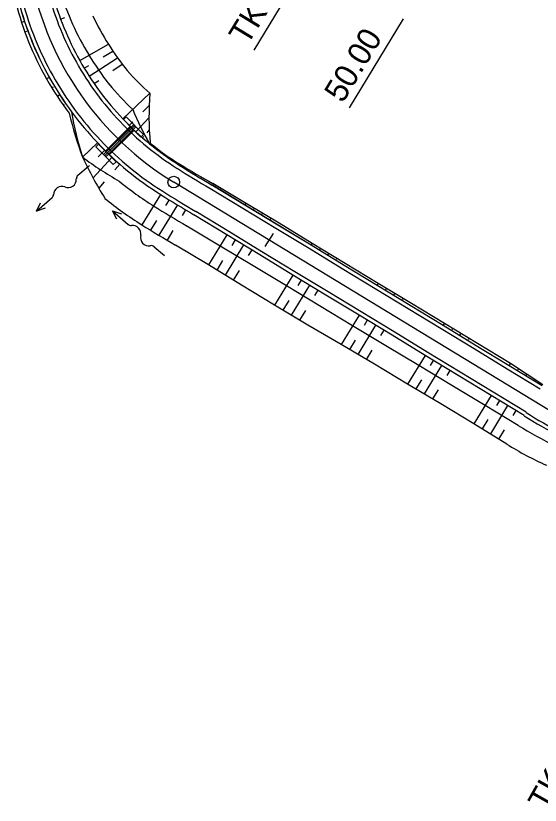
# Model space of a CAD drawing. Extents: x -481656 to -478728, y -1113199 to -1110710.
# Drawn here: x -479818.4 to -479750.6, y -1112835 to -1112732.9 of the extents above; entities that cross this region are included whole.
import ezdxf

# ---------------------------------------------------------------- set-up
doc = ezdxf.new("R2010")
doc.units = 0
for name, color, linetype in [('C1_HATCH_SLOPE_L', 7, 'Continuous'), ('C1_HATCH_SLOPE_R', 7, 'Continuous'), ('C1_HLBODY', 7, 'Continuous'), ('C1_HRANA_TELESO', 7, 'Continuous'), ('C1_KORUNA', 7, 'Continuous'), ('C1_OSA', 7, 'Continuous'), ('C1_PRIKOP', 7, 'Continuous'), ('C1_STANICENI', 7, 'Continuous'), ('C1_VOZOVKA', 7, 'Continuous'), ('C1_ZPEVKRAJ', 7, 'Continuous'), ('DRENÁŽ', 7, 'Continuous'), ('PLYN', 7, 'Continuous'), ('ŽLAB', 7, 'Continuous')]:
    doc.layers.add(name, color=color, linetype=linetype)

# ---------------------------------------------------------------- blocks, each defined once
blk = doc.blocks.new('A$C716')
at = {"layer": 'ŽLAB'}
for p, q in [((-5.015, 2.333), (-4.471, 3.623)), ((-4.01, 3.428), (-4.554, 2.138)), ((-4.01, 3.428), (-4.471, 3.623)), ((-5.17, 1.964), (-5.015, 2.333)), ((0, 0), (-5.093, 2.148)), ((-5.015, 2.333), (-0.383, 0.379)), ((-4.554, 2.138), (-5.015, 2.333)), ((-0.325, 0.517), (-4.496, 2.277)), ((-5.715, 0.674), (-5.17, 1.964)), ((-4.71, 1.77), (-5.254, 0.48)), ((-0.078, -0.184), (-5.171, 1.964)), ((-4.71, 1.77), (-5.17, 1.964)), ((-4.768, 1.632), (-0.597, -0.128)), ((0.161, 1.669), (-0.383, 0.379)), ((0.078, 0.184), (0.622, 1.474)), ((0.161, 1.669), (0.622, 1.474)), ((-5.254, 0.48), (-5.715, 0.674)), ((-0.538, 0.01), (-1.083, -1.28)), ((-0.078, -0.184), (-0.999, 0.204)), ((0.078, 0.184), (-0.844, 0.573)), ((-0.538, 0.01), (-0.383, 0.379)), ((-0.078, -0.184), (0.078, 0.184)), ((-0.622, -1.474), (-0.078, -0.184)), ((-1.083, -1.28), (-0.622, -1.474))]:
    blk.add_line(p, q, dxfattribs=at)
blk = doc.blocks.new('A$C70B')
at = {"layer": 'DRENÁŽ'}
for p, q in [((0.87, 0), (-0.87, 0)), ((6.86, 0.43), (7.97, 0)), ((7.97, 0), (5.28, 0)), ((7.97, 0), (6.86, -0.48))]:
    blk.add_line(p, q, dxfattribs=at)
for centre, radius, start, end in [((0.87, 0.58), 0.582, 269.6924, 322.7901), ((2.17, -0.42), 1.05, 24.4039, 142.0836), ((4.08, 0.59), 1.11, 210.8873, 317.3707), ((5.32, -0.64), 0.636, 85.9766, 131.7248)]:
    blk.add_arc(centre, radius, start, end, dxfattribs=at)

msp = doc.modelspace()

# ---------------------------------------------------------------- linework, layer by layer
at = {"layer": 'C1_HATCH_SLOPE_L'}
for p, q in [((-479817.25, -1112733.66), (-479817.64, -1112733.79)), ((-479817.01, -1112734.98), (-479817.2, -1112735.05)), ((-479816.81, -1112734.91), (-479816.81, -1112734.91)), ((-479814.05, -1112740.89), (-479814.41, -1112741.09)), ((-479813.56, -1112742.14), (-479813.73, -1112742.24)), ((-479813.39, -1112742.04), (-479813.39, -1112742.04)), ((-479812.69, -1112743.16), (-479813.01, -1112743.36)), ((-479812.11, -1112744.36), (-479812.26, -1112744.47)), ((-479811.96, -1112744.26), (-479811.96, -1112744.26)), ((-479807.8, -1112749.38), (-479809.74, -1112751.22)), ((-479806.87, -1112750.32), (-479807.73, -1112751.18)), ((-479805.92, -1112751.23), (-479808.41, -1112753.91)), ((-479808.84, -1112752.31), (-479809.1, -1112752.57)), ((-479804.94, -1112752.11), (-479805.59, -1112752.86)), ((-479806.95, -1112754.42), (-479807.66, -1112755.23)), ((-479799.65, -1112756.05), (-479802.1, -1112759.96)), ((-479798.55, -1112756.72), (-479799, -1112757.46)), ((-479797.48, -1112757.37), (-479799.88, -1112761.3)), ((-479796.42, -1112758.02), (-479796.86, -1112758.75)), ((-479800.2, -1112759.42), (-479800.95, -1112760.65)), ((-479798.06, -1112760.71), (-479798.8, -1112761.94)), ((-479791.08, -1112761.26), (-479793.45, -1112765.16)), ((-479790.01, -1112761.91), (-479790.45, -1112762.63)), ((-479788.94, -1112762.56), (-479791.32, -1112766.47)), ((-479787.87, -1112763.21), (-479788.31, -1112763.93)), ((-479791.63, -1112764.58), (-479792.38, -1112765.82)), ((-479789.5, -1112765.88), (-479790.25, -1112767.12)), ((-479782.53, -1112766.46), (-479784.91, -1112770.37)), ((-479781.46, -1112767.11), (-479781.89, -1112767.81)), ((-479780.4, -1112767.76), (-479782.77, -1112771.65)), ((-479779.33, -1112768.41), (-479779.75, -1112769.1)), ((-479783.08, -1112769.76), (-479783.84, -1112771.01)), ((-479780.93, -1112771.05), (-479781.69, -1112772.3)), ((-479773.99, -1112771.66), (-479776.31, -1112775.47)), ((-479772.92, -1112772.31), (-479773.33, -1112772.99)), ((-479771.85, -1112772.96), (-479774.15, -1112776.74)), ((-479770.79, -1112773.61), (-479771.2, -1112774.28)), ((-479774.49, -1112774.88), (-479775.23, -1112776.1)), ((-479772.34, -1112776.16), (-479773.07, -1112777.37)), ((-479765.45, -1112776.85), (-479767.7, -1112780.56)), ((-479763.31, -1112778.15), (-479765.56, -1112781.85)), ((-479764.38, -1112777.5), (-479764.78, -1112778.16)), ((-479762.24, -1112778.8), (-479762.64, -1112779.46)), ((-479765.9, -1112780.01), (-479766.63, -1112781.2)), ((-479763.76, -1112781.3), (-479764.48, -1112782.49)), ((-479756.9, -1112782.05), (-479759.12, -1112785.7)), ((-479754.77, -1112783.35), (-479757, -1112787.02)), ((-479755.83, -1112782.7), (-479756.22, -1112783.34)), ((-479753.7, -1112784), (-479754.08, -1112784.63)), ((-479757.34, -1112785.17), (-479758.06, -1112786.36)), ((-479755.2, -1112786.47), (-479755.93, -1112787.68))]:
    msp.add_line(p, q, dxfattribs=at)
at = {"layer": 'C1_HATCH_SLOPE_R'}
for p, q in [((-479812.59, -1112733.35), (-479812.04, -1112733.14)), ((-479810.12, -1112738.7), (-479806.4, -1112736.61)), ((-479807.07, -1112738.24), (-479805.83, -1112737.49)), ((-479808.91, -1112740.72), (-479805.23, -1112738.35)), ((-479809.53, -1112739.72), (-479808.92, -1112739.35)), ((-479805.82, -1112740.02), (-479804.61, -1112739.19)), ((-479808.25, -1112741.7), (-479807.64, -1112741.28)), ((-479804.54, -1112746.27), (-479801.03, -1112742.94)), ((-479801.96, -1112745.34), (-479801.14, -1112744.51)), ((-479803.71, -1112747.12), (-479803.25, -1112746.65)), ((-479802.86, -1112747.93), (-479801.17, -1112746.11)), ((-479801.4, -1112748.06), (-479801.12, -1112747.74)), ((-479801.98, -1112748.72), (-479801.84, -1112748.55)), ((-479797.25, -1112752.24), (-479797.18, -1112752.12)), ((-479796.21, -1112752.87), (-479796.21, -1112752.87)), ((-479796.17, -1112752.8), (-479796.13, -1112752.74)), ((-479795.15, -1112753.52), (-479795.05, -1112753.37)), ((-479794.08, -1112754.17), (-479794.07, -1112754.17)), ((-479794.02, -1112754.08), (-479793.98, -1112754.01)), ((-479788.74, -1112757.42), (-479788.6, -1112757.19)), ((-479787.67, -1112758.07), (-479787.67, -1112758.06)), ((-479787.6, -1112757.95), (-479787.53, -1112757.84)), ((-479786.6, -1112758.72), (-479786.46, -1112758.48)), ((-479785.53, -1112759.37), (-479785.53, -1112759.36)), ((-479785.46, -1112759.24), (-479785.39, -1112759.13)), ((-479780.19, -1112762.62), (-479780.04, -1112762.37)), ((-479779.05, -1112763.14), (-479778.97, -1112763.02)), ((-479779.13, -1112763.27), (-479779.12, -1112763.26)), ((-479778.06, -1112763.92), (-479777.9, -1112763.66)), ((-479776.99, -1112764.56), (-479776.99, -1112764.56)), ((-479776.91, -1112764.43), (-479776.84, -1112764.31)), ((-479771.65, -1112767.81), (-479771.49, -1112767.55)), ((-479770.5, -1112768.33), (-479770.42, -1112768.2)), ((-479770.58, -1112768.46), (-479770.58, -1112768.46)), ((-479769.51, -1112769.11), (-479769.35, -1112768.85)), ((-479768.45, -1112769.76), (-479768.44, -1112769.76)), ((-479768.36, -1112769.62), (-479768.28, -1112769.5)), ((-479763.11, -1112773.01), (-479762.94, -1112772.74)), ((-479761.95, -1112773.52), (-479761.87, -1112773.38)), ((-479762.04, -1112773.66), (-479762.04, -1112773.65)), ((-479760.97, -1112774.31), (-479760.8, -1112774.03)), ((-479759.9, -1112774.96), (-479759.9, -1112774.95)), ((-479759.82, -1112774.81), (-479759.73, -1112774.68)), ((-479754.56, -1112778.21), (-479754.39, -1112777.92)), ((-479753.49, -1112778.85), (-479753.49, -1112778.85)), ((-479753.42, -1112778.72), (-479753.34, -1112778.6)), ((-479752.43, -1112779.51), (-479752.29, -1112779.28)), ((-479751.36, -1112780.16), (-479751.36, -1112780.15)), ((-479751.3, -1112780.06), (-479751.24, -1112779.97))]:
    msp.add_line(p, q, dxfattribs=at)
at = {"layer": 'C1_HLBODY'}
msp.add_line((-479787.57, -1112737.36), (-479772.13, -1112711.98), dxfattribs=at)
msp.add_circle((-479797.96, -1112754.44), 0.75, dxfattribs=at)
at = {"layer": 'C1_HRANA_TELESO'}
for p, q in [((-479788.6, -1112757.19), (-479792.9, -1112754.64)), ((-479784.32, -1112759.77), (-479788.6, -1112757.19)), ((-479780.04, -1112762.37), (-479784.32, -1112759.77)), ((-479793.45, -1112765.16), (-479797.73, -1112762.59)), ((-479775.77, -1112764.96), (-479780.04, -1112762.37)), ((-479789.19, -1112767.78), (-479793.45, -1112765.16)), ((-479771.49, -1112767.55), (-479775.77, -1112764.96)), ((-479784.91, -1112770.37), (-479789.19, -1112767.78)), ((-479767.22, -1112770.14), (-479771.49, -1112767.55)), ((-479762.94, -1112772.74), (-479767.22, -1112770.14)), ((-479780.62, -1112772.94), (-479784.91, -1112770.37)), ((-479776.31, -1112775.47), (-479780.62, -1112772.94)), ((-479758.66, -1112775.33), (-479762.94, -1112772.74)), ((-479754.39, -1112777.92), (-479758.66, -1112775.33)), ((-479771.99, -1112778), (-479776.31, -1112775.47)), ((-479767.7, -1112780.56), (-479771.99, -1112778)), ((-479750.2, -1112780.65), (-479754.39, -1112777.92)), ((-479763.41, -1112783.14), (-479767.7, -1112780.56)), ((-479759.12, -1112785.7), (-479763.41, -1112783.14)), ((-479754.87, -1112788.33), (-479759.12, -1112785.7))]:
    msp.add_line(p, q, dxfattribs=at)
for centre, radius, start, end in [((-479777.08, -1112720.54), 42.66, 194.5096, 201.6717), ((-479777.98, -1112718.7), 33.59, 205.0483, 212.2201), ((-479777.25, -1112720.11), 42.67, 202.2915, 209.4535), ((-479778.09, -1112718.92), 33.38, 212.0163, 219.1868), ((-479779.16, -1112718.11), 33.1, 221.4387, 228.6289), ((-479777.39, -1112719.93), 42.63, 209.7635, 216.9258), ((-479765.9, -1112745.98), 35.26, 175.0636, 185.5386), ((-479768.84, -1112735.63), 43.77, 193.085, 200.8657), ((-479777.19, -1112720.26), 37.62, 230.7293, 237.8913), ((-479768.04, -1112732.04), 45.9, 204.698, 212.2574), ((-479737.85, -1112656.13), 112.84, 238.2814, 240.8033), ((-479777.22, -1112720.23), 46.87, 230.7782, 237.9402), ((-479727.35, -1112640.88), 140.59, 237.8841, 239.962), ((-479732.26, -1112752.32), 42.52, 237.8719, 245.7214)]:
    msp.add_arc(centre, radius, start, end, dxfattribs=at)
at = {"layer": 'C1_KORUNA'}
for p, q in [((-479788.74, -1112757.42), (-479793.01, -1112754.82)), ((-479784.47, -1112760.02), (-479788.74, -1112757.42)), ((-479791.08, -1112761.26), (-479795.35, -1112758.67)), ((-479780.19, -1112762.62), (-479784.47, -1112760.02)), ((-479786.8, -1112763.86), (-479791.08, -1112761.26)), ((-479775.92, -1112765.21), (-479780.19, -1112762.62)), ((-479782.53, -1112766.46), (-479786.8, -1112763.86)), ((-479771.65, -1112767.81), (-479775.92, -1112765.21)), ((-479778.26, -1112769.06), (-479782.53, -1112766.46)), ((-479767.38, -1112770.41), (-479771.65, -1112767.81)), ((-479773.99, -1112771.66), (-479778.26, -1112769.06)), ((-479763.11, -1112773.01), (-479767.38, -1112770.41)), ((-479769.72, -1112774.26), (-479773.99, -1112771.66)), ((-479758.84, -1112775.61), (-479763.11, -1112773.01)), ((-479765.45, -1112776.85), (-479769.72, -1112774.26)), ((-479754.56, -1112778.21), (-479758.84, -1112775.61)), ((-479761.17, -1112779.45), (-479765.45, -1112776.85)), ((-479750.29, -1112780.8), (-479754.56, -1112778.21)), ((-479756.9, -1112782.05), (-479761.17, -1112779.45)), ((-479752.63, -1112784.65), (-479756.9, -1112782.05))]:
    msp.add_line(p, q, dxfattribs=at)
for centre, radius, start, end in [((-479777.17, -1112720.27), 37.75, 194.8971, 202.0591), ((-479777.17, -1112720.27), 42.25, 194.8971, 202.0591), ((-479777.17, -1112720.27), 37.75, 202.0591, 209.2211), ((-479777.17, -1112720.27), 42.25, 202.0591, 209.2211), ((-479777.17, -1112720.27), 37.75, 209.2211, 216.383), ((-479777.17, -1112720.27), 42.25, 209.2211, 216.383), ((-479777.17, -1112720.27), 37.75, 216.383, 223.545), ((-479777.17, -1112720.27), 42.25, 216.383, 223.545), ((-479777.17, -1112720.27), 37.75, 223.545, 230.707), ((-479777.17, -1112720.27), 42.25, 223.545, 230.707), ((-479777.17, -1112720.27), 37.75, 230.707, 237.869), ((-479777.17, -1112720.27), 42.25, 230.707, 237.869), ((-479736.22, -1112656.84), 113.25, 237.3891, 239.9026), ((-479731.55, -1112649.14), 126.75, 237.5037, 239.7786), ((-479731.25, -1112752.03), 39.01, 236.7567, 244.5204)]:
    msp.add_arc(centre, radius, start, end, dxfattribs=at)
at = {"layer": 'C1_OSA'}
msp.add_line((-479749.36, -1112784), (-479797.96, -1112754.44), dxfattribs=at)
msp.add_arc((-479777.17, -1112720.27), 40, 143.5927, 238.6906, dxfattribs=at)
at = {"layer": 'C1_PRIKOP'}
for p, q in [((-479788.73, -1112757.41), (-479793, -1112754.81)), ((-479784.46, -1112760.01), (-479788.73, -1112757.41)), ((-479780.19, -1112762.61), (-479784.46, -1112760.01)), ((-479791.95, -1112762.71), (-479796.24, -1112760.13)), ((-479787.67, -1112765.29), (-479791.95, -1112762.71)), ((-479775.92, -1112765.21), (-479780.19, -1112762.61)), ((-479771.65, -1112767.8), (-479775.92, -1112765.21)), ((-479783.39, -1112767.86), (-479787.67, -1112765.29)), ((-479779.1, -1112770.44), (-479783.39, -1112767.86)), ((-479767.37, -1112770.4), (-479771.65, -1112767.8)), ((-479774.82, -1112773.02), (-479779.1, -1112770.44)), ((-479763.1, -1112773), (-479767.37, -1112770.4)), ((-479770.53, -1112775.6), (-479774.82, -1112773.02)), ((-479758.83, -1112775.6), (-479763.1, -1112773)), ((-479766.25, -1112778.18), (-479770.53, -1112775.6)), ((-479754.56, -1112778.2), (-479758.83, -1112775.6)), ((-479761.97, -1112780.76), (-479766.25, -1112778.18)), ((-479750.29, -1112780.8), (-479754.56, -1112778.2)), ((-479757.68, -1112783.33), (-479761.97, -1112780.76)), ((-479753.4, -1112785.91), (-479757.68, -1112783.33))]:
    msp.add_line(p, q, dxfattribs=at)
for centre, radius, start, end in [((-479777.63, -1112718.98), 36.63, 197.0336, 204.2005), ((-479777.17, -1112720.27), 42.26, 194.8971, 202.0591), ((-479777.8, -1112719.02), 36.46, 204.2517, 211.4189), ((-479777.17, -1112720.27), 42.26, 202.0591, 209.2211), ((-479777.85, -1112719.26), 36.3, 211.1291, 218.2951), ((-479777.17, -1112720.27), 42.26, 209.2211, 216.383), ((-479778.39, -1112718.89), 36.1, 219.2873, 226.4585), ((-479768.27, -1112737.78), 43.59, 189.9802, 197.9498), ((-479769.21, -1112730.94), 36.86, 202.5242, 210.1847), ((-479777.17, -1112720.27), 37.74, 230.707, 237.8689), ((-479783.02, -1112715.69), 44.45, 233.0586, 240.3217), ((-479736.23, -1112656.86), 113.22, 237.3888, 239.9029), ((-479777.16, -1112720.28), 43.98, 230.6919, 237.8539), ((-479730.23, -1112645.87), 131.95, 237.7903, 239.9863), ((-479720.14, -1112731.68), 63.62, 238.4773, 243.4026)]:
    msp.add_arc(centre, radius, start, end, dxfattribs=at)
at = {"layer": 'C1_STANICENI'}
for p, q in [((-479775.24, -1112744.85), (-479768.23, -1112733.32)), ((-479785.11, -1112761.09), (-479786.16, -1112762.79))]:
    msp.add_line(p, q, dxfattribs=at)
at = {"layer": 'C1_VOZOVKA'}
for p, q in [((-479789, -1112757.85), (-479793.27, -1112755.25)), ((-479784.73, -1112760.45), (-479789, -1112757.85)), ((-479790.82, -1112760.84), (-479795.09, -1112758.24)), ((-479786.54, -1112763.44), (-479790.82, -1112760.84)), ((-479780.45, -1112763.04), (-479784.73, -1112760.45)), ((-479776.18, -1112765.64), (-479780.45, -1112763.04)), ((-479782.27, -1112766.03), (-479786.54, -1112763.44)), ((-479778, -1112768.63), (-479782.27, -1112766.03)), ((-479771.91, -1112768.24), (-479776.18, -1112765.64)), ((-479767.64, -1112770.84), (-479771.91, -1112768.24)), ((-479773.73, -1112771.23), (-479778, -1112768.63)), ((-479769.46, -1112773.83), (-479773.73, -1112771.23)), ((-479763.37, -1112773.44), (-479767.64, -1112770.84)), ((-479765.18, -1112776.43), (-479769.46, -1112773.83)), ((-479759.09, -1112776.03), (-479763.37, -1112773.44)), ((-479760.91, -1112779.02), (-479765.18, -1112776.43)), ((-479754.82, -1112778.63), (-479759.09, -1112776.03)), ((-479756.64, -1112781.62), (-479760.91, -1112779.02)), ((-479750.55, -1112781.23), (-479754.82, -1112778.63)), ((-479752.37, -1112784.22), (-479756.64, -1112781.62))]:
    msp.add_line(p, q, dxfattribs=at)
for centre, radius, start, end in [((-479777.17, -1112720.27), 38.25, 194.8971, 202.0591), ((-479777.17, -1112720.27), 41.75, 194.8971, 202.0591), ((-479777.17, -1112720.27), 38.25, 202.0591, 209.2211), ((-479777.17, -1112720.27), 41.75, 202.0591, 209.2211), ((-479777.17, -1112720.27), 38.25, 209.2211, 216.383), ((-479777.17, -1112720.27), 41.75, 209.2211, 216.383), ((-479777.17, -1112720.27), 38.25, 216.383, 223.545), ((-479777.17, -1112720.27), 41.75, 216.383, 223.545), ((-479777.17, -1112720.27), 38.25, 223.545, 230.707), ((-479777.17, -1112720.27), 41.75, 223.545, 230.707), ((-479777.17, -1112720.27), 38.25, 230.707, 237.869), ((-479777.17, -1112720.27), 41.75, 230.707, 237.869), ((-479735.7, -1112655.98), 114.75, 237.4032, 239.8874), ((-479732.07, -1112650), 125.25, 237.4922, 239.7911), ((-479733.92, -1112756.78), 33.07, 236.0926, 245.1432)]:
    msp.add_arc(centre, radius, start, end, dxfattribs=at)
at = {"layer": 'C1_ZPEVKRAJ'}
for p, q in [((-479789, -1112757.85), (-479793.27, -1112755.25)), ((-479784.73, -1112760.45), (-479789, -1112757.85)), ((-479790.82, -1112760.84), (-479795.09, -1112758.24)), ((-479786.54, -1112763.44), (-479790.82, -1112760.84)), ((-479780.45, -1112763.04), (-479784.73, -1112760.45)), ((-479776.18, -1112765.64), (-479780.45, -1112763.04)), ((-479782.27, -1112766.03), (-479786.54, -1112763.44)), ((-479778, -1112768.63), (-479782.27, -1112766.03)), ((-479771.91, -1112768.24), (-479776.18, -1112765.64)), ((-479767.64, -1112770.84), (-479771.91, -1112768.24)), ((-479773.73, -1112771.23), (-479778, -1112768.63)), ((-479769.46, -1112773.83), (-479773.73, -1112771.23)), ((-479763.37, -1112773.44), (-479767.64, -1112770.84)), ((-479765.18, -1112776.43), (-479769.46, -1112773.83)), ((-479759.09, -1112776.03), (-479763.37, -1112773.44)), ((-479760.91, -1112779.02), (-479765.18, -1112776.43)), ((-479754.82, -1112778.63), (-479759.09, -1112776.03)), ((-479756.64, -1112781.62), (-479760.91, -1112779.02)), ((-479750.55, -1112781.23), (-479754.82, -1112778.63)), ((-479752.37, -1112784.22), (-479756.64, -1112781.62))]:
    msp.add_line(p, q, dxfattribs=at)
for centre, radius, start, end in [((-479777.17, -1112720.27), 38.25, 194.8971, 202.0591), ((-479777.17, -1112720.27), 41.75, 194.8971, 202.0591), ((-479777.17, -1112720.27), 38.25, 202.0591, 209.2211), ((-479777.17, -1112720.27), 41.75, 202.0591, 209.2211), ((-479777.17, -1112720.27), 38.25, 209.2211, 216.383), ((-479777.17, -1112720.27), 41.75, 209.2211, 216.383), ((-479777.17, -1112720.27), 38.25, 216.383, 223.545), ((-479777.17, -1112720.27), 41.75, 216.383, 223.545), ((-479777.17, -1112720.27), 38.25, 223.545, 230.707), ((-479777.17, -1112720.27), 41.75, 223.545, 230.707), ((-479777.17, -1112720.27), 38.25, 230.707, 237.869), ((-479777.17, -1112720.27), 41.75, 230.707, 237.869), ((-479735.7, -1112655.98), 114.75, 237.4032, 239.8874), ((-479732.07, -1112650), 125.25, 237.4922, 239.7911), ((-479733.92, -1112756.78), 33.07, 236.0926, 245.1432)]:
    msp.add_arc(centre, radius, start, end, dxfattribs=at)

# ---------------------------------------------------------------- block references
at = {"layer": 'PLYN'}
for p, rotation in [((-479809.69, -1112752.98), -139.03471960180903), ((-479799.83, -1112763.37), 139.26816149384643)]:
    msp.add_blockref('A$C70B', p, dxfattribs=dict(at, rotation=rotation))
at = {"layer": 'ŽLAB', "rotation": 67.70351917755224}
msp.add_blockref('A$C716', (-479802.98, -1112747.13), dxfattribs=at)

# ---------------------------------------------------------------- texts
at = {"layer": 'C1_HLBODY'}
for s, height, rotation, p in [('TK 0.664426', 3, 58.6906, (-479788.42, -1112736.84)), ('TK 0.580883', 2.999, 60.6378, (-479749.66, -1112835.95))]:
    msp.add_text(s, height=height, rotation=rotation, dxfattribs=at).set_placement(p)
at = {"layer": 'C1_STANICENI'}
msp.add_text('50.00', height=2.999, rotation=58.6906, dxfattribs=at).set_placement((-479776.1, -1112744.33))

doc.saveas('drawing.dxf')
